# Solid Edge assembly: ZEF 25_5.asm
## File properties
Title: Zylinder
Author: bmolnar
Template: iso metric assembly.asm
Last saved by: bmolnar
Revision: 8
Application: Solid Edge
Username: bmolnar
Dokumentum tartalom típus: 1
Document Number: ZEF 25/5
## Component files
Mutter.par
Profilrohr.par
Kolbenstange.par
Kit_2.par
Kit_1.par
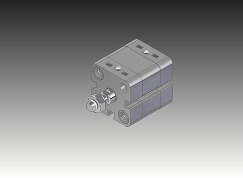
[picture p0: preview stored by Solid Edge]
